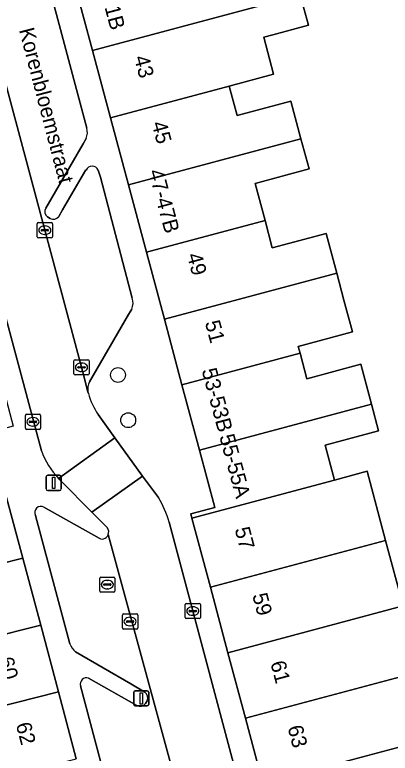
# Model space of a CAD drawing. Extents: x 162542 to 163147, y 380779 to 381521.
# Drawn here: x 162947.55 to 162972.3, y 380933.68 to 380982.36 of the extents above; entities that cross this region are included whole.
import ezdxf

# ---------------------------------------------------------------- set-up
doc = ezdxf.new("R2010")
doc.units = 0
for name, color, linetype in [('IMGEO_Boom', 7, 'Continuous'), ('IMGEO_Erf', 7, 'Continuous'), ('IMGEO_Kolk', 7, 'Continuous'), ('IMGEO_Lichtmast', 7, 'Continuous'), ('IMGEO_Openbare_ruimte_label', 7, 'Continuous'), ('IMGEO_Pand', 7, 'Continuous'), ('IMGEO_Pand_nummerreeks', 7, 'Continuous'), ('IMGEO_Parkeervlak_open', 7, 'Continuous'), ('IMGEO_Rijbaan_lokaal_open', 7, 'Continuous'), ('IMGEO_Rioolput', 7, 'Continuous'), ('IMGEO_Voetpad_open', 7, 'Continuous')]:
    doc.layers.add(name, color=color, linetype=linetype)

msp = doc.modelspace()

# ---------------------------------------------------------------- linework, layer by layer
at = {"layer": 'IMGEO_Boom'}
for centre in [(162954.351, 380958.615), (162955.023, 380955.633)]:
    msp.add_circle(centre, 0.489, dxfattribs=at)
at = {"layer": 'IMGEO_Erf'}
msp.add_lwpolyline([(162966.37, 380983.677), (162966.906, 380981.666), (162964.551, 380981.038), (162963.963, 380980.881), (162964.612, 380978.448), (162961.681, 380977.664), (162962.197, 380975.728), (162965.748, 380976.675), (162966.413, 380974.183), (162966.943, 380972.196), (162963.39, 380971.248), (162964.042, 380968.803), (162964.523, 380966.999), (162968.072, 380967.945), (162968.772, 380965.322), (162969.246, 380963.543), (162969.804, 380961.448), (162966.233, 380960.497), (162966.351, 380960.053), (162966.8, 380958.369), (162970.363, 380959.32), (162971.064, 380956.693), (162971.533, 380954.934), (162967.997, 380953.99), (162968.612, 380951.687), (162970.771, 380952.263), (162971.988, 380947.7), (162973.14, 380943.385)], dxfattribs=at)
at = {"layer": 'IMGEO_Kolk'}
for p, q in [((162949.029, 380967.731), (162949.029, 380968.583)), ((162949.104, 380968.657), (162949.956, 380968.657)), ((162950.03, 380968.583), (162950.03, 380967.731)), ((162949.288, 380968.151), (162949.288, 380968.163)), ((162949.726, 380968.114), (162949.328, 380968.114)), ((162949.331, 380968.2), (162949.729, 380968.2)), ((162949.517, 380968.437), (162949.542, 380968.437)), ((162949.772, 380968.163), (162949.772, 380968.151)), ((162949.956, 380967.657), (162949.104, 380967.657)), ((162949.54, 380967.877), (162949.515, 380967.877)), ((162951.447, 380958.692), (162951.447, 380959.544)), ((162951.522, 380959.618), (162952.374, 380959.618)), ((162951.935, 380959.398), (162951.96, 380959.398)), ((162952.448, 380959.544), (162952.448, 380958.692)), ((162951.706, 380959.112), (162951.706, 380959.124)), ((162952.144, 380959.075), (162951.746, 380959.075)), ((162951.749, 380959.161), (162952.147, 380959.161)), ((162951.958, 380958.838), (162951.933, 380958.838)), ((162952.19, 380959.124), (162952.19, 380959.112)), ((162952.374, 380958.618), (162951.522, 380958.618)), ((162948.244, 380955.098), (162948.244, 380955.95)), ((162948.319, 380956.024), (162949.171, 380956.024)), ((162949.245, 380955.95), (162949.245, 380955.098)), ((162948.503, 380955.518), (162948.503, 380955.53)), ((162948.941, 380955.481), (162948.543, 380955.481)), ((162948.546, 380955.567), (162948.944, 380955.567)), ((162948.732, 380955.804), (162948.757, 380955.804)), ((162948.987, 380955.53), (162948.987, 380955.518)), ((162949.171, 380955.024), (162948.319, 380955.024)), ((162948.755, 380955.244), (162948.73, 380955.244)), ((162958.78, 380942.622), (162958.78, 380943.474)), ((162958.855, 380943.548), (162959.707, 380943.548)), ((162959.268, 380943.328), (162959.293, 380943.328)), ((162959.781, 380943.474), (162959.781, 380942.622)), ((162954.647, 380941.933), (162954.647, 380942.785)), ((162954.722, 380942.859), (162955.574, 380942.859)), ((162955.648, 380942.785), (162955.648, 380941.933)), ((162959.039, 380943.042), (162959.039, 380943.054)), ((162959.477, 380943.005), (162959.079, 380943.005)), ((162959.082, 380943.091), (162959.48, 380943.091)), ((162959.291, 380942.768), (162959.266, 380942.768)), ((162959.523, 380943.054), (162959.523, 380943.042)), ((162954.906, 380942.353), (162954.906, 380942.365)), ((162955.344, 380942.316), (162954.946, 380942.316)), ((162954.949, 380942.402), (162955.347, 380942.402)), ((162955.135, 380942.639), (162955.16, 380942.639)), ((162955.39, 380942.365), (162955.39, 380942.353)), ((162959.707, 380942.548), (162958.855, 380942.548)), ((162955.574, 380941.859), (162954.722, 380941.859)), ((162955.158, 380942.079), (162955.133, 380942.079))]:
    msp.add_line(p, q, dxfattribs=at)
for points in [[(162949.029, 380967.731), (162949.029, 380968.583)], [(162949.104, 380968.657), (162949.956, 380968.657)], [(162950.03, 380968.583), (162950.03, 380967.731)], [(162949.956, 380967.657), (162949.104, 380967.657)], [(162951.447, 380958.692), (162951.447, 380959.544)], [(162951.522, 380959.618), (162952.374, 380959.618)], [(162952.448, 380959.544), (162952.448, 380958.692)], [(162952.374, 380958.618), (162951.522, 380958.618)], [(162948.244, 380955.098), (162948.244, 380955.95)], [(162948.319, 380956.024), (162949.171, 380956.024)], [(162949.245, 380955.95), (162949.245, 380955.098)], [(162949.171, 380955.024), (162948.319, 380955.024)], [(162958.78, 380942.622), (162958.78, 380943.474)], [(162958.855, 380943.548), (162959.707, 380943.548)], [(162959.781, 380943.474), (162959.781, 380942.622)], [(162954.647, 380941.933), (162954.647, 380942.785)], [(162954.722, 380942.859), (162955.574, 380942.859)], [(162955.648, 380942.785), (162955.648, 380941.933)], [(162959.707, 380942.548), (162958.855, 380942.548)], [(162955.574, 380941.859), (162954.722, 380941.859)]]:
    msp.add_lwpolyline(points, dxfattribs=at)
for centre, radius, start, end in [((162949.106, 380968.581), 0.0765, 91.552, 178.448), ((162949.106, 380968.581), 0.0765, 91.552, 178.448), ((162949.954, 380968.581), 0.0765, 1.552, 88.448), ((162949.954, 380968.581), 0.0765, 1.552, 88.448), ((162949.328, 380968.16), 0.0403, 85.8775, 175.7526), ((162949.325, 380968.15), 0.0366, 178.938, 274.7102), ((162949.729, 380968.157), 0.043, 264.8664, 352.4533), ((162949.733, 380968.162), 0.0386, 1.7309, 96.639), ((162949.106, 380967.733), 0.0765, 181.552, 268.448), ((162949.106, 380967.733), 0.0765, 181.552, 268.448), ((162949.954, 380967.733), 0.0765, 271.552, 358.448), ((162949.954, 380967.733), 0.0765, 271.552, 358.448), ((162951.524, 380959.542), 0.0765, 91.552, 178.448), ((162951.524, 380959.542), 0.0765, 91.552, 178.448), ((162952.372, 380959.542), 0.0765, 1.552, 88.448), ((162952.372, 380959.542), 0.0765, 1.552, 88.448), ((162951.746, 380959.121), 0.0403, 85.8775, 175.7526), ((162951.743, 380959.111), 0.0366, 178.938, 274.7102), ((162952.147, 380959.118), 0.043, 264.8664, 352.4533), ((162952.151, 380959.123), 0.0386, 1.7309, 96.639), ((162951.524, 380958.694), 0.0765, 181.552, 268.448), ((162951.524, 380958.694), 0.0765, 181.552, 268.448), ((162952.372, 380958.694), 0.0765, 271.552, 358.448), ((162952.372, 380958.694), 0.0765, 271.552, 358.448), ((162948.321, 380955.948), 0.0765, 91.552, 178.448), ((162948.321, 380955.948), 0.0765, 91.552, 178.448), ((162949.169, 380955.948), 0.0765, 1.552, 88.448), ((162949.169, 380955.948), 0.0765, 1.552, 88.448), ((162948.543, 380955.527), 0.0403, 85.8775, 175.7526), ((162948.54, 380955.517), 0.0366, 178.938, 274.7102), ((162948.944, 380955.524), 0.043, 264.8664, 352.4533), ((162948.948, 380955.529), 0.0386, 1.7309, 96.639), ((162948.321, 380955.1), 0.0765, 181.552, 268.448), ((162948.321, 380955.1), 0.0765, 181.552, 268.448), ((162949.169, 380955.1), 0.0765, 271.552, 358.448), ((162949.169, 380955.1), 0.0765, 271.552, 358.448), ((162958.857, 380943.472), 0.0765, 91.552, 178.448), ((162958.857, 380943.472), 0.0765, 91.552, 178.448), ((162959.705, 380943.472), 0.0765, 1.552, 88.448), ((162959.705, 380943.472), 0.0765, 1.552, 88.448), ((162954.724, 380942.783), 0.0765, 91.552, 178.448), ((162954.724, 380942.783), 0.0765, 91.552, 178.448), ((162955.572, 380942.783), 0.0765, 1.552, 88.448), ((162955.572, 380942.783), 0.0765, 1.552, 88.448), ((162959.079, 380943.051), 0.0403, 85.8775, 175.7526), ((162959.076, 380943.041), 0.0366, 178.938, 274.7102), ((162959.48, 380943.048), 0.043, 264.8664, 352.4533), ((162959.484, 380943.053), 0.0386, 1.7309, 96.639), ((162954.946, 380942.362), 0.0403, 85.8775, 175.7526), ((162954.943, 380942.352), 0.0366, 178.938, 274.7102), ((162955.347, 380942.359), 0.043, 264.8664, 352.4533), ((162955.351, 380942.364), 0.0386, 1.7309, 96.639), ((162958.857, 380942.624), 0.0765, 181.552, 268.448), ((162958.857, 380942.624), 0.0765, 181.552, 268.448), ((162959.705, 380942.624), 0.0765, 271.552, 358.448), ((162959.705, 380942.624), 0.0765, 271.552, 358.448), ((162954.724, 380941.935), 0.0765, 181.552, 268.448), ((162954.724, 380941.935), 0.0765, 181.552, 268.448), ((162955.572, 380941.935), 0.0765, 271.552, 358.448), ((162955.572, 380941.935), 0.0765, 271.552, 358.448)]:
    msp.add_arc(centre, radius, start, end, dxfattribs=at)
for centre, major_axis, ratio, start_param, end_param in [((162949.516, 380968.157), (-0.387, 0.002), 0.722429, 4.712389, 7.853982), ((162949.541, 380968.157), (-0.39, 0.002), 0.717154, 1.570796, 4.712389), ((162951.934, 380959.118), (-0.387, 0.002), 0.722429, 4.712389, 7.853982), ((162951.959, 380959.118), (-0.39, 0.002), 0.717154, 1.570796, 4.712389), ((162948.731, 380955.524), (-0.387, 0.002), 0.722429, 4.712389, 7.853982), ((162948.756, 380955.524), (-0.39, 0.002), 0.717154, 1.570796, 4.712389), ((162959.267, 380943.048), (-0.387, 0.002), 0.722429, 4.712389, 7.853982), ((162959.292, 380943.048), (-0.39, 0.002), 0.717154, 1.570796, 4.712389), ((162955.134, 380942.359), (-0.387, 0.002), 0.722429, 4.712389, 7.853982), ((162955.159, 380942.359), (-0.39, 0.002), 0.717154, 1.570796, 4.712389)]:
    msp.add_ellipse(centre, major_axis=major_axis, ratio=ratio, start_param=start_param, end_param=end_param, dxfattribs=at)
at = {"layer": 'IMGEO_Lichtmast'}
for p, q in [((162949.616, 380951.097), (162949.616, 380951.897)), ((162949.616, 380951.897), (162949.616, 380951.097)), ((162949.716, 380951.997), (162950.506, 380951.997)), ((162950.506, 380951.997), (162949.716, 380951.997)), ((162950.606, 380951.897), (162950.606, 380951.097)), ((162950.606, 380951.097), (162950.606, 380951.897)), ((162950.506, 380950.997), (162949.716, 380950.997)), ((162949.716, 380950.997), (162950.506, 380950.997)), ((162955.387, 380936.893), (162955.387, 380937.693)), ((162955.387, 380937.693), (162955.387, 380936.893)), ((162955.487, 380937.793), (162956.277, 380937.793)), ((162956.277, 380937.793), (162955.487, 380937.793)), ((162956.377, 380937.693), (162956.377, 380936.893)), ((162956.377, 380936.893), (162956.377, 380937.693)), ((162956.277, 380936.793), (162955.487, 380936.793)), ((162955.487, 380936.793), (162956.277, 380936.793))]:
    msp.add_line(p, q, dxfattribs=at)
for points in [[(162950.036, 380951.872), (162950.186, 380951.872), (162950.186, 380951.122), (162950.036, 380951.122), (162950.036, 380951.872)], [(162955.807, 380937.668), (162955.957, 380937.668), (162955.957, 380936.918), (162955.807, 380936.918), (162955.807, 380937.668)]]:
    msp.add_lwpolyline(points, dxfattribs=at)
for centre, start, end in [((162949.716, 380951.897), 90, 180), ((162949.716, 380951.897), 90, 180), ((162950.506, 380951.897), 0, 90), ((162950.506, 380951.897), 360, 90), ((162949.716, 380951.097), 180, 270), ((162949.716, 380951.097), 180, 270), ((162950.506, 380951.097), 270, 0), ((162950.506, 380951.097), 270, 0), ((162955.487, 380937.693), 90, 180), ((162955.487, 380937.693), 90, 180), ((162956.277, 380937.693), 0, 90), ((162956.277, 380937.693), 360, 90), ((162955.487, 380936.893), 180, 270), ((162955.487, 380936.893), 180, 270), ((162956.277, 380936.893), 270, 0), ((162956.277, 380936.893), 270, 0)]:
    msp.add_arc(centre, 0.1, start, end, dxfattribs=at)
at = {"layer": 'IMGEO_Pand'}
for points in [[(162965.739, 380986.043), (162963.384, 380985.414), (162959.888, 380984.481), (162959.341, 380986.53), (162951.486, 380984.429), (162952.671, 380980), (162964.035, 380983.04), (162966.37, 380983.677)], [(162966.37, 380983.677), (162964.035, 380983.04), (162952.671, 380980), (162953.855, 380975.571), (162961.681, 380977.664), (162964.612, 380978.448), (162963.963, 380980.881), (162964.551, 380981.038), (162966.906, 380981.666)], [(162953.855, 380975.571), (162955.04, 380971.141), (162966.413, 380974.183), (162965.748, 380976.675), (162962.197, 380975.728), (162961.681, 380977.664)], [(162963.39, 380971.248), (162966.943, 380972.196), (162966.413, 380974.183), (162955.04, 380971.141), (162956.224, 380966.712), (162964.042, 380968.803)], [(162964.042, 380968.803), (162956.224, 380966.712), (162957.409, 380962.283), (162968.772, 380965.322), (162968.072, 380967.945), (162964.523, 380966.999)], [(162969.246, 380963.543), (162968.772, 380965.322), (162957.409, 380962.283), (162958.562, 380957.97), (162966.351, 380960.053), (162966.233, 380960.497), (162969.804, 380961.448)], [(162970.363, 380959.32), (162966.8, 380958.369), (162966.351, 380960.053), (162958.562, 380957.97), (162959.715, 380953.658), (162971.064, 380956.693)], [(162967.997, 380953.99), (162971.533, 380954.934), (162971.064, 380956.693), (162959.715, 380953.658), (162960.725, 380949.882), (162959.154, 380949.463), (162959.229, 380949.183), (162968.612, 380951.687)], [(162968.612, 380951.687), (162959.229, 380949.183), (162960.448, 380944.613), (162971.988, 380947.7), (162970.771, 380952.263)], [(162940.002, 380944.475), (162941.116, 380944.772), (162948.08, 380946.529), (162946.925, 380950.857), (162935.267, 380947.76), (162935.902, 380945.38), (162939.505, 380946.341)], [(162971.988, 380947.7), (162960.448, 380944.613), (162961.599, 380940.299), (162973.14, 380943.385)], [(162940.002, 380944.475), (162937.472, 380943.802), (162938.107, 380941.425), (162937.118, 380941.161), (162937.644, 380939.132), (162938.08, 380939.246), (162942.26, 380940.359), (162949.255, 380942.123), (162948.08, 380946.529), (162941.116, 380944.772)], [(162962.749, 380935.986), (162974.29, 380939.073), (162973.14, 380943.385), (162961.599, 380940.299)], [(162938.788, 380934.719), (162939.242, 380934.838), (162943.404, 380935.945), (162950.43, 380937.718), (162949.255, 380942.123), (162942.26, 380940.359), (162938.08, 380939.246), (162937.644, 380939.132)], [(162962.749, 380935.986), (162963.9, 380931.672), (162975.439, 380934.767), (162974.29, 380939.073)], [(162938.788, 380934.719), (162939.932, 380930.306), (162940.404, 380930.429), (162944.548, 380931.532), (162951.605, 380933.312), (162950.43, 380937.718), (162943.404, 380935.945), (162939.242, 380934.838)], [(162963.9, 380931.672), (162965.05, 380927.359), (162976.44, 380930.405), (162976.59, 380930.451), (162975.439, 380934.767)]]:
    msp.add_lwpolyline(points, close=True, dxfattribs=at)
at = {"layer": 'IMGEO_Parkeervlak_open'}
for points in [[(162937.182, 381014.315), (162952.035, 380958.794), (162952.371, 380957.505)], [(162952.294, 380974.883), (162944.054, 381005.688), (162943.849, 381006.417)], [(162949.584, 380969.606), (162952.049, 380973.856), (162952.251, 380974.214)], [(162952.253, 380972.12), (162952.228, 380972.149), (162950.696, 380969.498), (162950.446, 380969.052)], [(162955.294, 380963.679), (162953.201, 380971.654), (162953.049, 380972.123)], [(162949.875, 380968.927), (162949.711, 380969.032)], [(162952.463, 380958.155), (162955.037, 380962.597), (162955.257, 380962.961)], [(162953.1, 380947.851), (162949.472, 380949.897)], [(162948.915, 380949.353), (162951.181, 380940.891)], [(162959.887, 380921.279), (162959.089, 380927.574), (162959.022, 380928.201), (162958.873, 380929.023), (162958.51, 380930.441), (162953.706, 380948.086)], [(162951.543, 380940.365), (162955.201, 380938.254), (162956.13, 380937.703)], [(162955.602, 380936.829), (162952.399, 380938.629)], [(162951.876, 380938.111), (162953.192, 380933.156)], [(162956.271, 380937.123), (162956.167, 380936.948)]]:
    msp.add_lwpolyline(points, dxfattribs=at)
for centre, radius, start, end in [((162951.353, 380974.608), 0.98, 336.3313, 16.3134), ((162952.652, 380971.93), 0.442, 25.9584, 154.4734), ((162949.937, 380969.383), 0.417, 147.7, 237.2519), ((162950.078, 380969.366), 0.484, 245.2018, 319.4943), ((162954.365, 380963.367), 0.98, 335.5342, 18.5659), ((162953.35, 380957.698), 0.997, 152.7313, 191.1566), ((162949.27, 380949.546), 0.404, 60.0682, 208.5788), ((162953.3, 380948.21), 0.411, 240.8809, 299.6863), ((162953.258, 380948.271), 0.485, 300.5374, 337.6151), ((162952.545, 380941.442), 1.471, 201.9985, 227.074), ((162952.276, 380938.231), 0.417, 72.784, 196.6656), ((162955.841, 380937.326), 0.475, 334.7577, 52.5697), ((162955.823, 380937.183), 0.417, 238.0719, 325.7156)]:
    msp.add_arc(centre, radius, start, end, dxfattribs=at)
at = {"layer": 'IMGEO_Rijbaan_lokaal_open'}
for points in [[(162932.068, 381018.083), (162933.706, 381011.552), (162935.911, 381003.519), (162937.085, 380999.244), (162949.301, 380953.613)], [(162952.401, 380957.391), (162952.371, 380957.505), (162952.035, 380958.794), (162937.182, 381014.315)], [(162950.434, 380951.798), (162954.148, 380954.475), (162953.05, 380956.004)], [(162957.014, 380950.527), (162955.963, 380951.953), (162952.632, 380949.57), (162953.655, 380948.534)], [(162963.098, 380928.709), (162957.72, 380948.914)], [(162953.706, 380948.086), (162958.51, 380930.441), (162958.873, 380929.023), (162959.022, 380928.201), (162959.089, 380927.574), (162959.887, 380921.279), (162960.14, 380920.317), (162961.096, 380916.787), (162965.699, 380899.709), (162968.749, 380900.529), (162964.033, 380918.276), (162963.872, 380919.033)]]:
    msp.add_lwpolyline(points, dxfattribs=at)
msp.add_lwpolyline([(162954.148, 380954.475), (162950.434, 380951.798), (162950.512, 380951.718), (162950.591, 380951.639), (162952.632, 380949.57), (162955.963, 380951.953)], close=True, dxfattribs=at)
for centre, radius, start, end in [((162956.993, 380958.694), 4.774, 195.8461, 214.3052), ((162954.302, 380955.474), 5.336, 200.4087, 223.5396), ((162952.034, 380947.386), 5.887, 15.0386, 32.2388), ((162953.264, 380948.263), 0.476, 338.2047, 34.7844)]:
    msp.add_arc(centre, radius, start, end, dxfattribs=at)
at = {"layer": 'IMGEO_Rioolput'}
for p, q in [((162953.146, 380944.366), (162953.146, 380945.218)), ((162953.221, 380945.292), (162954.073, 380945.292)), ((162954.147, 380945.218), (162954.147, 380944.366)), ((162953.405, 380944.786), (162953.405, 380944.798)), ((162953.843, 380944.749), (162953.445, 380944.749)), ((162953.448, 380944.835), (162953.846, 380944.835)), ((162953.634, 380945.072), (162953.659, 380945.072)), ((162953.889, 380944.798), (162953.889, 380944.786)), ((162954.073, 380944.292), (162953.221, 380944.292)), ((162953.657, 380944.512), (162953.632, 380944.512))]:
    msp.add_line(p, q, dxfattribs=at)
for points in [[(162953.146, 380944.366), (162953.146, 380945.218)], [(162953.221, 380945.292), (162954.073, 380945.292)], [(162954.147, 380945.218), (162954.147, 380944.366)], [(162954.073, 380944.292), (162953.221, 380944.292)]]:
    msp.add_lwpolyline(points, dxfattribs=at)
for centre, radius, start, end in [((162953.223, 380945.216), 0.0765, 91.552, 178.448), ((162953.223, 380945.216), 0.0765, 91.552, 178.448), ((162954.071, 380945.216), 0.0765, 1.552, 88.448), ((162954.071, 380945.216), 0.0765, 1.552, 88.448), ((162953.445, 380944.795), 0.0403, 85.8775, 175.7526), ((162953.442, 380944.785), 0.0366, 178.938, 274.7102), ((162953.846, 380944.792), 0.043, 264.8664, 352.4533), ((162953.85, 380944.797), 0.0386, 1.7309, 96.639), ((162953.223, 380944.368), 0.0765, 181.552, 268.448), ((162953.223, 380944.368), 0.0765, 181.552, 268.448), ((162954.071, 380944.368), 0.0765, 271.552, 358.448), ((162954.071, 380944.368), 0.0765, 271.552, 358.448)]:
    msp.add_arc(centre, radius, start, end, dxfattribs=at)
for centre, major_axis, ratio, start_param, end_param in [((162953.633, 380944.792), (-0.387, 0.002), 0.722429, 4.712389, 7.853982), ((162953.658, 380944.792), (-0.39, 0.002), 0.717154, 1.570796, 4.712389)]:
    msp.add_ellipse(centre, major_axis=major_axis, ratio=ratio, start_param=start_param, end_param=end_param, dxfattribs=at)
at = {"layer": 'IMGEO_Voetpad_open'}
for points in [[(162949.301, 380953.613), (162937.085, 380999.244), (162935.911, 381003.519), (162933.706, 381011.552), (162932.068, 381018.083)], [(162943.849, 381006.417), (162944.054, 381005.688), (162952.294, 380974.883)], [(162939.191, 380986.073), (162940.379, 380981.636), (162941.572, 380977.176), (162942.72, 380972.887), (162943.922, 380968.397), (162945.051, 380964.179), (162946.17, 380959.997), (162947.441, 380955.248), (162945.866, 380954.827), (162946.925, 380950.857), (162948.08, 380946.529), (162949.255, 380942.123), (162950.43, 380937.718), (162951.605, 380933.312)], [(162966.504, 380921.889), (162966.201, 380923.045), (162965.05, 380927.359), (162963.9, 380931.672), (162962.749, 380935.986), (162961.599, 380940.299), (162960.448, 380944.613), (162959.229, 380949.183), (162959.154, 380949.463), (162960.725, 380949.882), (162959.715, 380953.658), (162958.562, 380957.97), (162957.409, 380962.283), (162956.224, 380966.712), (162955.04, 380971.141), (162953.855, 380975.571), (162952.671, 380980), (162951.486, 380984.429)], [(162952.251, 380974.214), (162952.049, 380973.856), (162949.584, 380969.606)], [(162950.446, 380969.052), (162950.696, 380969.498), (162952.228, 380972.149), (162952.253, 380972.12)], [(162953.049, 380972.123), (162953.201, 380971.654), (162955.294, 380963.679)], [(162949.711, 380969.032), (162949.875, 380968.927)], [(162955.257, 380962.961), (162955.037, 380962.597), (162952.463, 380958.155)], [(162952.371, 380957.505), (162952.401, 380957.391)], [(162953.05, 380956.004), (162954.148, 380954.475), (162955.963, 380951.953), (162957.014, 380950.527)], [(162953.655, 380948.534), (162952.632, 380949.57), (162950.591, 380951.639), (162950.512, 380951.718), (162950.434, 380951.798)], [(162949.472, 380949.897), (162953.1, 380947.851)], [(162951.181, 380940.891), (162948.915, 380949.353)], [(162957.72, 380948.914), (162963.098, 380928.709)], [(162956.13, 380937.703), (162955.201, 380938.254), (162951.543, 380940.365)], [(162952.399, 380938.629), (162955.602, 380936.829)], [(162953.192, 380933.156), (162951.876, 380938.111)], [(162956.167, 380936.948), (162956.271, 380937.123)]]:
    msp.add_lwpolyline(points, dxfattribs=at)
for centre, radius, start, end in [((162951.353, 380974.608), 0.98, 336.3313, 16.3134), ((162952.652, 380971.93), 0.442, 25.9584, 154.4734), ((162949.937, 380969.383), 0.417, 147.7, 237.2519), ((162950.078, 380969.366), 0.484, 245.2018, 319.4943), ((162954.365, 380963.367), 0.98, 335.5342, 18.5659), ((162953.35, 380957.698), 0.997, 152.7313, 191.1566), ((162956.993, 380958.694), 4.774, 195.8461, 214.3052), ((162954.302, 380955.474), 5.336, 200.4087, 223.5396), ((162952.034, 380947.386), 5.887, 15.0386, 32.2388), ((162949.27, 380949.546), 0.404, 60.0682, 208.5788), ((162953.264, 380948.263), 0.476, 338.2047, 34.7844), ((162953.3, 380948.21), 0.411, 240.8809, 299.6863), ((162953.258, 380948.271), 0.485, 300.5374, 337.6151), ((162952.545, 380941.442), 1.471, 201.9985, 227.074), ((162952.276, 380938.231), 0.417, 72.784, 196.6656), ((162955.841, 380937.326), 0.475, 334.7577, 52.5697), ((162955.823, 380937.183), 0.417, 238.0719, 325.7156)]:
    msp.add_arc(centre, radius, start, end, dxfattribs=at)

# ---------------------------------------------------------------- texts
at = {"layer": 'IMGEO_Openbare_ruimte_label'}
msp.add_text('Korenbloemstraat', height=1, rotation=284.6619, dxfattribs=at).set_placement((162947.822, 380981.365))
at = {"layer": 'IMGEO_Pand_nummerreeks'}
for s, rotation, p in [('41-41B', 284.9769, (162952.767, 380985.445)), ('43', 284.9718, (162955.4, 380979.546)), ('45', 284.9718, (162956.561, 380975.205)), ('47-47B', 284.9654, (162956.352, 380972.041)), ('49', 284.9718, (162958.883, 380966.524)), ('51', 284.9712, (162960.074, 380962.074)), ('53-53B', 284.9712, (162959.859, 380958.925)), ('55-55A', 284.9769, (162961.023, 380954.572)), ('57', 284.9332, (162962.033, 380948.453)), ('59', 284.9332, (162963.195, 380944.097)), ('60', 284.9366, (162946.459, 380939.879)), ('61', 284.9332, (162964.386, 380939.63)), ('62', 284.9366, (162947.608, 380935.576)), ('63', 284.9332, (162965.518, 380935.384))]:
    msp.add_text(s, height=1, rotation=rotation, dxfattribs=at).set_placement(p)

doc.saveas('drawing.dxf')
